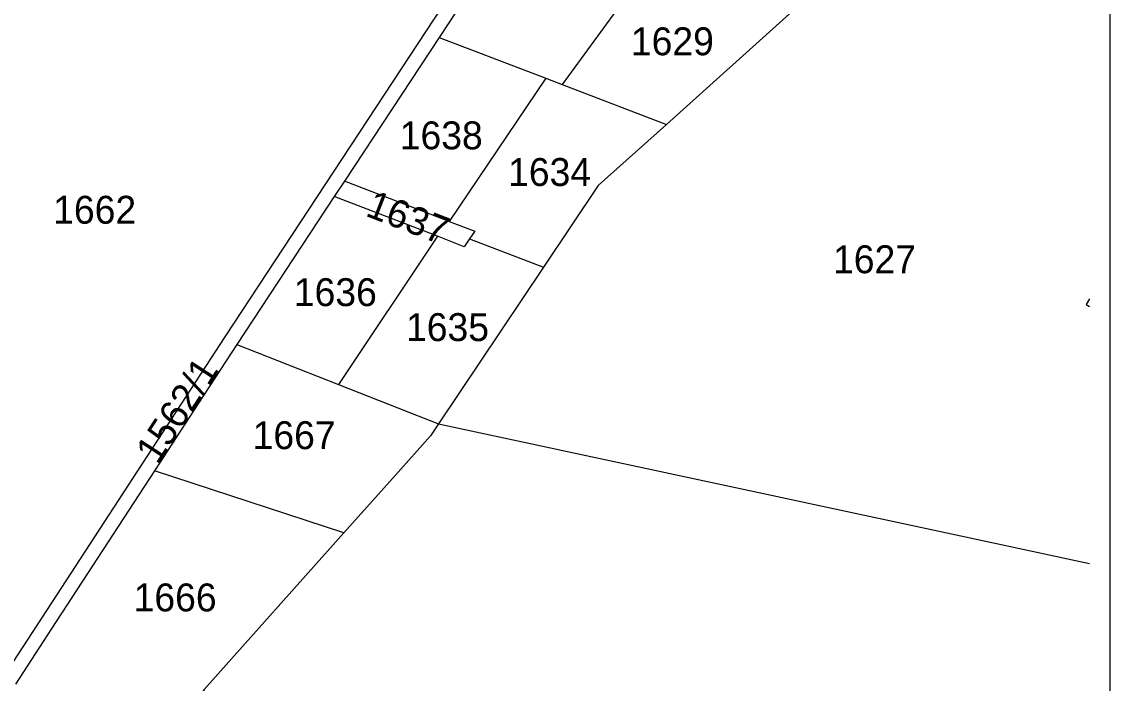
# Model space of a CAD drawing. Extents: x -583889 to -582839, y -1166553 to -1165068.
# Drawn here: x -583111.8 to -582838.7, y -1165500.8 to -1165334.9 of the extents above; entities that cross this region are included whole.
import ezdxf

# ---------------------------------------------------------------- set-up
doc = ezdxf.new("R2010")
doc.units = 0
for name, color, linetype in [('_parcely přehledka', 7, 'Continuous'), ('Hranice parcel', 7, 'Continuous'), ('Parcelní čísla', 7, 'Continuous')]:
    doc.layers.add(name, color=color, linetype=linetype)

msp = doc.modelspace()

# ---------------------------------------------------------------- linework, layer by layer
at = {"layer": '_parcely přehledka'}
msp.add_lwpolyline([(-583888.67, -1166552.78), (-582838.67, -1166552.78), (-582838.67, -1165067.78), (-583888.67, -1165067.78), (-583888.67, -1166552.78)], dxfattribs=at)
at = {"layer": 'Hranice parcel'}
for p, q in [((-582987.21, -1165308.59), (-583007.11, -1165338.81)), ((-582954.72, -1165321.03), (-582976.18, -1165350.65)), ((-582918.34, -1165332.17), (-582950.06, -1165360.65)), ((-583007.11, -1165338.81), (-583030.89, -1165374.9)), ((-583007.11, -1165338.81), (-582980.36, -1165349.05)), ((-582980.36, -1165349.05), (-583004.55, -1165384.98)), ((-582980.36, -1165349.05), (-582976.18, -1165350.65)), ((-582976.18, -1165350.65), (-582950.06, -1165360.65)), ((-583030.89, -1165374.9), (-583033.44, -1165378.77)), ((-583004.55, -1165384.98), (-583030.89, -1165374.9)), ((-583033.44, -1165378.77), (-583057.85, -1165415.82)), ((-583007.52, -1165388.67), (-583033.44, -1165378.77)), ((-583007.52, -1165388.67), (-583032.38, -1165425.88)), ((-582999.45, -1165389.32), (-582980.91, -1165396.48)), ((-582980.91, -1165396.48), (-583007.29, -1165435.79)), ((-583057.85, -1165415.82), (-583032.38, -1165425.88)), ((-583032.38, -1165425.88), (-583007.29, -1165435.79)), ((-583031.01, -1165463.11), (-583078.55, -1165447.56))]:
    msp.add_line(p, q, dxfattribs=at)
for points in [[(-583150.03, -1165547.02), (-583146.45, -1165545.26), (-583081.48, -1165445.65), (-583060.78, -1165413.9), (-582999.79, -1165321.21), (-583000.42, -1165318.79)], [(-582950.06, -1165360.65), (-582967.17, -1165376.01), (-582980.91, -1165396.48)], [(-583004.55, -1165384.98), (-582998.17, -1165387.42), (-582999.45, -1165389.32)], [(-582999.45, -1165389.32), (-583000.82, -1165391.34), (-583007.52, -1165388.67)], [(-582843.89, -1165404.37), (-582844.73, -1165405.8), (-582843.89, -1165406.35)], [(-583057.85, -1165415.82), (-583067.46, -1165430.56), (-583078.55, -1165447.56)], [(-583007.29, -1165435.79), (-583009.3, -1165438.8), (-583018.06, -1165448.61), (-583031.01, -1165463.11)], [(-583007.29, -1165435.79), (-582885.16, -1165461.96), (-582843.89, -1165470.8)], [(-583078.55, -1165447.56), (-583104.44, -1165487.27), (-583113.44, -1165501.07)], [(-583031.01, -1165463.11), (-583066.05, -1165502.38), (-583075.83, -1165515.92)]]:
    msp.add_lwpolyline(points, dxfattribs=at)

# ---------------------------------------------------------------- texts
at = {"layer": 'Parcelní čísla'}
for s, p in [('1629', (-582958.97, -1165343.3)), ('1638', (-583016.98, -1165366.89)), ('1634', (-582989.79, -1165376.09)), ('1662', (-583103.96, -1165385.56)), ('1627', (-582908.24, -1165397.98)), ('1636', (-583043.56, -1165406.23)), ('1635', (-583015.41, -1165415)), ('1667', (-583053.9, -1165442.11)), ('1666', (-583083.77, -1165482.81))]:
    msp.add_text(s, height=7, dxfattribs=at).set_placement(p)
for s, rotation, p in [('1637', 339, (-583025.86, -1165383.5)), ('1562/1', 57, (-583077.76, -1165446.22))]:
    msp.add_text(s, height=7, rotation=rotation, dxfattribs=at).set_placement(p)

doc.saveas('drawing.dxf')
